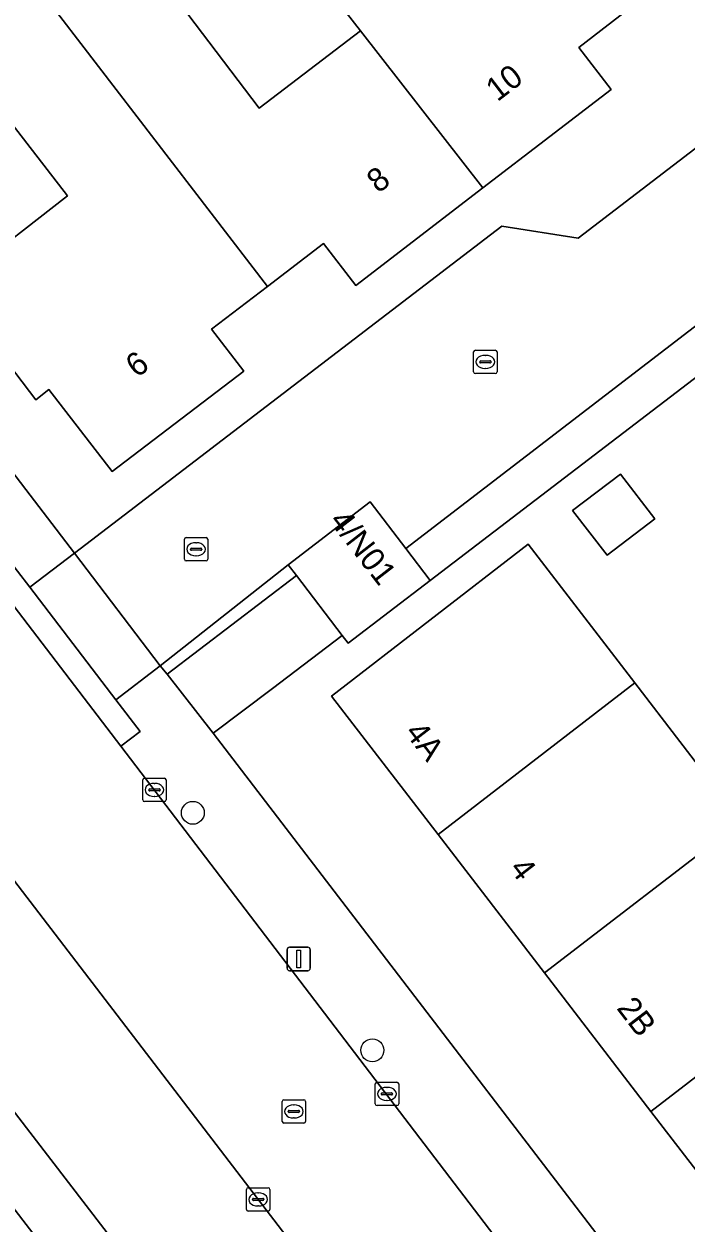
# Model space of a CAD drawing. Extents: x 159352 to 160617, y 385888 to 387323.
# Drawn here: x 159956.1 to 159984.4, y 386578.7 to 386630 of the extents above; entities that cross this region are included whole.
import ezdxf

# ---------------------------------------------------------------- set-up
doc = ezdxf.new("R2010")
doc.units = 0
for name, color, linetype in [('IMGEO_Boom', 7, 'Continuous'), ('IMGEO_Erf', 7, 'Continuous'), ('IMGEO_Kolk', 7, 'Continuous'), ('IMGEO_Lichtmast', 7, 'Continuous'), ('IMGEO_Pand', 7, 'Continuous'), ('IMGEO_Pand_nummerreeks', 7, 'Continuous'), ('IMGEO_Parkeervlak_open', 7, 'Continuous'), ('IMGEO_Rijbaan_lokaal_open', 7, 'Continuous'), ('IMGEO_Rioolput', 7, 'Continuous'), ('IMGEO_Voetpad_open', 7, 'Continuous')]:
    doc.layers.add(name, color=color, linetype=linetype)

msp = doc.modelspace()

# ---------------------------------------------------------------- linework, layer by layer
at = {"layer": 'IMGEO_Boom'}
for centre in [(159963.305, 386596.274), (159970.984, 386586.121)]:
    msp.add_circle(centre, 0.489, dxfattribs=at)
at = {"layer": 'IMGEO_Erf'}
for points in [[(159968.972, 386640.663), (159965.595, 386645.082), (159961.243, 386641.763), (159957.042, 386638.558), (159960.348, 386634.04), (159966.149, 386626.39), (159970.474, 386629.706), (159968.795, 386631.865), (159973.148, 386635.198)], [(159981.022, 386607.284), (159979.545, 386609.197), (159981.598, 386610.757), (159983.062, 386608.837)], [(160000.448, 386586.263), (159998.468, 386584.763), (159996.488, 386583.263), (160000.418, 386578.153), (159992.002, 386571.674), (159987.45, 386577.592), (159982.897, 386583.509), (159978.345, 386589.427), (159973.792, 386595.344), (159969.24, 386601.262), (159977.654, 386607.752), (159982.214, 386601.823), (159986.064, 386596.816), (159988.035, 386598.335), (159989.997, 386599.848), (159991.471, 386597.918), (159989.5, 386596.415), (159987.529, 386594.911), (159991.317, 386589.987), (159995.02, 386585.171), (159997.005, 386586.694), (159998.964, 386588.196)]]:
    msp.add_lwpolyline(points, close=True, dxfattribs=at)
for points in [[(159937.429, 386634.583), (159958.24, 386607.374), (159976.527, 386621.358), (159979.779, 386620.834), (159993.835, 386631.612), (159991.763, 386638.279), (160000, 386644.604)], [(159982.189, 386630.821), (159979.811, 386628.993), (159981.19, 386627.2), (159978.567, 386625.185), (159975.702, 386622.984), (159970.27, 386618.81), (159968.896, 386620.608), (159966.497, 386618.775), (159964.106, 386616.948), (159965.48, 386615.15), (159959.85, 386610.86), (159957.151, 386614.363), (159956.59, 386613.93), (159954.86, 386616.18), (159955.43, 386616.606), (159954.74, 386617.53), (159954.855, 386617.619), (159953.582, 386619.257), (159957.947, 386622.649), (159953.335, 386628.585), (159949.885, 386633.073), (159945.395, 386629.643), (159944.701, 386630.546)], [(160000, 386626.477), (159973.45, 386606.21), (159969.948, 386603.524), (159969.698, 386603.852), (159966.706, 386601.593), (159964.176, 386599.682), (159987.621, 386569.07)], [(159973.106, 386556.66), (159922.14, 386622.955)]]:
    msp.add_lwpolyline(points, dxfattribs=at)
at = {"layer": 'IMGEO_Kolk'}
for p, q in [((159975.315, 386615.124), (159975.315, 386615.976)), ((159975.39, 386616.05), (159976.242, 386616.05)), ((159975.617, 386615.593), (159976.015, 386615.593)), ((159975.803, 386615.83), (159975.828, 386615.83)), ((159976.316, 386615.976), (159976.316, 386615.124)), ((159975.574, 386615.544), (159975.574, 386615.556)), ((159976.012, 386615.507), (159975.614, 386615.507)), ((159975.826, 386615.27), (159975.801, 386615.27)), ((159976.058, 386615.556), (159976.058, 386615.544)), ((159976.242, 386615.05), (159975.39, 386615.05)), ((159962.944, 386607.113), (159962.944, 386607.965)), ((159963.019, 386608.039), (159963.871, 386608.039)), ((159963.945, 386607.965), (159963.945, 386607.113)), ((159963.203, 386607.533), (159963.203, 386607.545)), ((159963.641, 386607.496), (159963.243, 386607.496)), ((159963.246, 386607.582), (159963.644, 386607.582)), ((159963.432, 386607.819), (159963.457, 386607.819)), ((159963.687, 386607.545), (159963.687, 386607.533)), ((159963.871, 386607.039), (159963.019, 386607.039)), ((159963.455, 386607.259), (159963.43, 386607.259)), ((159961.163, 386596.825), (159961.163, 386597.677)), ((159961.238, 386597.751), (159962.09, 386597.751)), ((159962.164, 386597.677), (159962.164, 386596.825)), ((159961.422, 386597.245), (159961.422, 386597.257)), ((159961.86, 386597.208), (159961.462, 386597.208)), ((159961.465, 386597.294), (159961.863, 386597.294)), ((159961.651, 386597.531), (159961.676, 386597.531)), ((159961.906, 386597.257), (159961.906, 386597.245)), ((159962.09, 386596.751), (159961.238, 386596.751)), ((159961.674, 386596.971), (159961.649, 386596.971)), ((159971.108, 386583.83), (159971.108, 386584.682)), ((159971.183, 386584.756), (159972.035, 386584.756)), ((159971.596, 386584.536), (159971.621, 386584.536)), ((159972.109, 386584.682), (159972.109, 386583.83)), ((159971.367, 386584.25), (159971.367, 386584.262)), ((159971.805, 386584.213), (159971.407, 386584.213)), ((159971.41, 386584.299), (159971.808, 386584.299)), ((159971.619, 386583.976), (159971.594, 386583.976)), ((159971.851, 386584.262), (159971.851, 386584.25)), ((159972.035, 386583.756), (159971.183, 386583.756)), ((159965.674, 386580.245), (159966.526, 386580.245)), ((159965.599, 386579.319), (159965.599, 386580.171)), ((159965.858, 386579.739), (159965.858, 386579.751)), ((159965.901, 386579.788), (159966.299, 386579.788)), ((159966.087, 386580.025), (159966.112, 386580.025)), ((159966.342, 386579.751), (159966.342, 386579.739)), ((159966.6, 386580.171), (159966.6, 386579.319)), ((159966.526, 386579.245), (159965.674, 386579.245)), ((159966.296, 386579.702), (159965.898, 386579.702)), ((159966.11, 386579.465), (159966.085, 386579.465))]:
    msp.add_line(p, q, dxfattribs=at)
for points in [[(159975.315, 386615.124), (159975.315, 386615.976)], [(159975.39, 386616.05), (159976.242, 386616.05)], [(159976.316, 386615.976), (159976.316, 386615.124)], [(159976.242, 386615.05), (159975.39, 386615.05)], [(159962.944, 386607.113), (159962.944, 386607.965)], [(159963.019, 386608.039), (159963.871, 386608.039)], [(159963.945, 386607.965), (159963.945, 386607.113)], [(159963.871, 386607.039), (159963.019, 386607.039)], [(159961.163, 386596.825), (159961.163, 386597.677)], [(159961.238, 386597.751), (159962.09, 386597.751)], [(159962.164, 386597.677), (159962.164, 386596.825)], [(159962.09, 386596.751), (159961.238, 386596.751)], [(159971.108, 386583.83), (159971.108, 386584.682)], [(159971.183, 386584.756), (159972.035, 386584.756)], [(159972.109, 386584.682), (159972.109, 386583.83)], [(159972.035, 386583.756), (159971.183, 386583.756)], [(159965.674, 386580.245), (159966.526, 386580.245)], [(159965.599, 386579.319), (159965.599, 386580.171)], [(159966.6, 386580.171), (159966.6, 386579.319)], [(159966.526, 386579.245), (159965.674, 386579.245)]]:
    msp.add_lwpolyline(points, dxfattribs=at)
for centre, radius, start, end in [((159975.392, 386615.974), 0.0765, 91.552, 178.448), ((159975.392, 386615.974), 0.0765, 91.552, 178.448), ((159975.614, 386615.553), 0.0403, 85.8775, 175.7526), ((159976.019, 386615.555), 0.0386, 1.7309, 96.639), ((159976.24, 386615.974), 0.0765, 1.552, 88.448), ((159976.24, 386615.974), 0.0765, 1.552, 88.448), ((159975.392, 386615.126), 0.0765, 181.552, 268.448), ((159975.392, 386615.126), 0.0765, 181.552, 268.448), ((159975.611, 386615.543), 0.0366, 178.938, 274.7102), ((159976.015, 386615.55), 0.043, 264.8664, 352.4533), ((159976.24, 386615.126), 0.0765, 271.552, 358.448), ((159976.24, 386615.126), 0.0765, 271.552, 358.448), ((159963.021, 386607.963), 0.0765, 91.552, 178.448), ((159963.021, 386607.963), 0.0765, 91.552, 178.448), ((159963.869, 386607.963), 0.0765, 1.552, 88.448), ((159963.869, 386607.963), 0.0765, 1.552, 88.448), ((159963.243, 386607.542), 0.0403, 85.8775, 175.7526), ((159963.24, 386607.532), 0.0366, 178.938, 274.7102), ((159963.644, 386607.539), 0.043, 264.8664, 352.4533), ((159963.648, 386607.544), 0.0386, 1.7309, 96.639), ((159963.021, 386607.115), 0.0765, 181.552, 268.448), ((159963.021, 386607.115), 0.0765, 181.552, 268.448), ((159963.869, 386607.115), 0.0765, 271.552, 358.448), ((159963.869, 386607.115), 0.0765, 271.552, 358.448), ((159961.24, 386597.675), 0.0765, 91.552, 178.448), ((159961.24, 386597.675), 0.0765, 91.552, 178.448), ((159962.088, 386597.675), 0.0765, 1.552, 88.448), ((159962.088, 386597.675), 0.0765, 1.552, 88.448), ((159961.462, 386597.254), 0.0403, 85.8775, 175.7526), ((159961.459, 386597.244), 0.0366, 178.938, 274.7102), ((159961.863, 386597.251), 0.043, 264.8664, 352.4533), ((159961.867, 386597.256), 0.0386, 1.7309, 96.639), ((159961.24, 386596.827), 0.0765, 181.552, 268.448), ((159961.24, 386596.827), 0.0765, 181.552, 268.448), ((159962.088, 386596.827), 0.0765, 271.552, 358.448), ((159962.088, 386596.827), 0.0765, 271.552, 358.448), ((159971.185, 386584.68), 0.0765, 91.552, 178.448), ((159971.185, 386584.68), 0.0765, 91.552, 178.448), ((159972.033, 386584.68), 0.0765, 1.552, 88.448), ((159972.033, 386584.68), 0.0765, 1.552, 88.448), ((159971.185, 386583.832), 0.0765, 181.552, 268.448), ((159971.185, 386583.832), 0.0765, 181.552, 268.448), ((159971.407, 386584.259), 0.0403, 85.8775, 175.7526), ((159971.404, 386584.249), 0.0366, 178.938, 274.7102), ((159971.808, 386584.256), 0.043, 264.8664, 352.4533), ((159971.812, 386584.261), 0.0386, 1.7309, 96.639), ((159972.033, 386583.832), 0.0765, 271.552, 358.448), ((159972.033, 386583.832), 0.0765, 271.552, 358.448), ((159965.676, 386580.169), 0.0765, 91.552, 178.448), ((159965.676, 386580.169), 0.0765, 91.552, 178.448), ((159966.524, 386580.169), 0.0765, 1.552, 88.448), ((159966.524, 386580.169), 0.0765, 1.552, 88.448), ((159965.898, 386579.748), 0.0403, 85.8775, 175.7526), ((159965.895, 386579.738), 0.0366, 178.938, 274.7102), ((159966.299, 386579.745), 0.043, 264.8664, 352.4533), ((159966.303, 386579.75), 0.0386, 1.7309, 96.639), ((159965.676, 386579.321), 0.0765, 181.552, 268.448), ((159965.676, 386579.321), 0.0765, 181.552, 268.448), ((159966.524, 386579.321), 0.0765, 271.552, 358.448), ((159966.524, 386579.321), 0.0765, 271.552, 358.448)]:
    msp.add_arc(centre, radius, start, end, dxfattribs=at)
for centre, major_axis, ratio, start_param, end_param in [((159975.802, 386615.55), (-0.387, 0.002), 0.722429, 4.712389, 7.853982), ((159975.827, 386615.55), (-0.39, 0.002), 0.717154, 1.570796, 4.712389), ((159963.431, 386607.539), (-0.387, 0.002), 0.722429, 4.712389, 7.853982), ((159963.456, 386607.539), (-0.39, 0.002), 0.717154, 1.570796, 4.712389), ((159961.65, 386597.251), (-0.387, 0.002), 0.722429, 4.712389, 7.853982), ((159961.675, 386597.251), (-0.39, 0.002), 0.717154, 1.570796, 4.712389), ((159971.595, 386584.256), (-0.387, 0.002), 0.722429, 4.712389, 7.853982), ((159971.62, 386584.256), (-0.39, 0.002), 0.717154, 1.570796, 4.712389), ((159966.086, 386579.745), (-0.387, 0.002), 0.722429, 4.712389, 7.853982), ((159966.111, 386579.745), (-0.39, 0.002), 0.717154, 1.570796, 4.712389)]:
    msp.add_ellipse(centre, major_axis=major_axis, ratio=ratio, start_param=start_param, end_param=end_param, dxfattribs=at)
at = {"layer": 'IMGEO_Lichtmast'}
for p, q in [((159967.436, 386590.525), (159968.226, 386590.525)), ((159968.226, 386590.525), (159967.436, 386590.525)), ((159967.336, 386589.625), (159967.336, 386590.425)), ((159967.336, 386590.425), (159967.336, 386589.625)), ((159968.326, 386590.425), (159968.326, 386589.625)), ((159968.326, 386589.625), (159968.326, 386590.425)), ((159968.226, 386589.525), (159967.436, 386589.525)), ((159967.436, 386589.525), (159968.226, 386589.525))]:
    msp.add_line(p, q, dxfattribs=at)
msp.add_lwpolyline([(159967.756, 386590.4), (159967.906, 386590.4), (159967.906, 386589.65), (159967.756, 386589.65), (159967.756, 386590.4)], dxfattribs=at)
for centre, start, end in [((159967.436, 386590.425), 90, 180), ((159967.436, 386590.425), 90, 180), ((159968.226, 386590.425), 0, 90), ((159968.226, 386590.425), 360, 90), ((159967.436, 386589.625), 180, 270), ((159967.436, 386589.625), 180, 270), ((159968.226, 386589.625), 270, 0), ((159968.226, 386589.625), 270, 0)]:
    msp.add_arc(centre, 0.1, start, end, dxfattribs=at)
at = {"layer": 'IMGEO_Pand'}
for points in [[(159982.189, 386630.821), (159972.52, 386643.37), (159968.972, 386640.663), (159973.148, 386635.198), (159968.795, 386631.865), (159970.474, 386629.706), (159975.702, 386622.984), (159978.567, 386625.185), (159981.19, 386627.2), (159979.811, 386628.993)], [(159975.702, 386622.984), (159970.474, 386629.706), (159966.149, 386626.39), (159960.348, 386634.04), (159956.855, 386631.322), (159966.497, 386618.775), (159968.896, 386620.608), (159970.27, 386618.81)], [(159956.855, 386631.322), (159953.335, 386628.585), (159957.947, 386622.649), (159953.582, 386619.257), (159954.855, 386617.619), (159954.74, 386617.53), (159955.43, 386616.606), (159954.86, 386616.18), (159956.59, 386613.93), (159957.151, 386614.363), (159959.85, 386610.86), (159965.48, 386615.15), (159964.106, 386616.948), (159966.497, 386618.775)], [(159981.598, 386610.757), (159979.545, 386609.197), (159981.022, 386607.284), (159983.062, 386608.837)], [(159967.388, 386606.878), (159967.735, 386606.424), (159969.698, 386603.852), (159969.948, 386603.524), (159973.45, 386606.21), (159972.409, 386607.573), (159970.89, 386609.564)], [(159982.214, 386601.823), (159977.654, 386607.752), (159969.24, 386601.262), (159973.792, 386595.344)], [(159986.765, 386595.905), (159986.064, 386596.816), (159982.214, 386601.823), (159973.792, 386595.344), (159978.345, 386589.427)], [(159991.317, 386589.987), (159987.529, 386594.911), (159986.765, 386595.905), (159978.345, 386589.427), (159982.897, 386583.509)], [(159995.869, 386584.068), (159995.02, 386585.171), (159991.317, 386589.987), (159982.897, 386583.509), (159987.45, 386577.592)]]:
    msp.add_lwpolyline(points, close=True, dxfattribs=at)
at = {"layer": 'IMGEO_Parkeervlak_open'}
for points in [[(159977.383, 386565.02), (159950.703, 386599.839), (159931.787, 386624.553)], [(159931.288, 386622.222), (159927.899, 386619.615), (159971.446, 386562.962), (159974.502, 386565.275)]]:
    msp.add_lwpolyline(points, dxfattribs=at)
at = {"layer": 'IMGEO_Rijbaan_lokaal_open'}
for points in [[(160000, 386628.741), (160015.231, 386640.426), (160007.623, 386650.457), (160000, 386644.604), (159991.763, 386638.279), (159993.835, 386631.612), (159979.779, 386620.834), (159976.527, 386621.358), (159958.24, 386607.374), (159961.914, 386602.559), (159967.388, 386606.878), (159970.89, 386609.564), (159972.409, 386607.573)], [(159934.436, 386632.803), (159928.787, 386628.473), (159931.787, 386624.553), (159950.703, 386599.839), (159977.383, 386565.02), (159978.763, 386563.271), (159980.449, 386561.077), (159985.98, 386565.362), (159960.23, 386599.121), (159954.454, 386606.66), (159934.758, 386632.371), (159934.721, 386632.417)]]:
    msp.add_lwpolyline(points, close=True, dxfattribs=at)
at = {"layer": 'IMGEO_Rioolput'}
for p, q in [((159967.126, 386583.082), (159967.126, 386583.934)), ((159967.201, 386584.008), (159968.053, 386584.008)), ((159968.127, 386583.934), (159968.127, 386583.082)), ((159967.385, 386583.502), (159967.385, 386583.514)), ((159967.823, 386583.465), (159967.425, 386583.465)), ((159967.428, 386583.551), (159967.826, 386583.551)), ((159967.614, 386583.788), (159967.639, 386583.788)), ((159967.869, 386583.514), (159967.869, 386583.502)), ((159968.053, 386583.008), (159967.201, 386583.008)), ((159967.637, 386583.228), (159967.612, 386583.228))]:
    msp.add_line(p, q, dxfattribs=at)
for points in [[(159967.126, 386583.082), (159967.126, 386583.934)], [(159967.201, 386584.008), (159968.053, 386584.008)], [(159968.127, 386583.934), (159968.127, 386583.082)], [(159968.053, 386583.008), (159967.201, 386583.008)]]:
    msp.add_lwpolyline(points, dxfattribs=at)
for centre, radius, start, end in [((159967.203, 386583.932), 0.0765, 91.552, 178.448), ((159967.203, 386583.932), 0.0765, 91.552, 178.448), ((159968.051, 386583.932), 0.0765, 1.552, 88.448), ((159968.051, 386583.932), 0.0765, 1.552, 88.448), ((159967.425, 386583.511), 0.0403, 85.8775, 175.7526), ((159967.422, 386583.501), 0.0366, 178.938, 274.7102), ((159967.826, 386583.508), 0.043, 264.8664, 352.4533), ((159967.83, 386583.513), 0.0386, 1.7309, 96.639), ((159967.203, 386583.084), 0.0765, 181.552, 268.448), ((159967.203, 386583.084), 0.0765, 181.552, 268.448), ((159968.051, 386583.084), 0.0765, 271.552, 358.448), ((159968.051, 386583.084), 0.0765, 271.552, 358.448)]:
    msp.add_arc(centre, radius, start, end, dxfattribs=at)
for centre, major_axis, ratio, start_param, end_param in [((159967.613, 386583.508), (-0.387, 0.002), 0.722429, 4.712389, 7.853982), ((159967.638, 386583.508), (-0.39, 0.002), 0.717154, 1.570796, 4.712389)]:
    msp.add_ellipse(centre, major_axis=major_axis, ratio=ratio, start_param=start_param, end_param=end_param, dxfattribs=at)
at = {"layer": 'IMGEO_Voetpad_open'}
for points in [[(160000, 386626.477), (160013.533, 386636.86), (160016.316, 386638.995), (160015.782, 386639.699), (160015.231, 386640.426), (160000, 386628.741), (159972.409, 386607.573), (159973.45, 386606.21)], [(159956.329, 386605.923), (159955.28, 386607.292), (159954.454, 386606.66), (159960.23, 386599.121), (159961.056, 386599.753), (159960.019, 386601.107)], [(159958.24, 386607.374), (159956.329, 386605.923), (159960.019, 386601.107), (159961.914, 386602.559)], [(159961.914, 386602.559), (159962.211, 386602.204), (159967.735, 386606.424), (159967.388, 386606.878)], [(159969.698, 386603.852), (159967.735, 386606.424), (159962.211, 386602.204), (159964.176, 386599.682), (159966.706, 386601.593)], [(159962.211, 386602.204), (159961.914, 386602.559), (159960.019, 386601.107), (159961.056, 386599.753), (159960.23, 386599.121), (159985.98, 386565.362), (159988.838, 386567.467), (159987.679, 386568.993), (159987.659, 386569.019), (159987.64, 386569.044), (159987.621, 386569.07), (159964.176, 386599.682)]]:
    msp.add_lwpolyline(points, close=True, dxfattribs=at)
for points in [[(159934.436, 386632.803), (159934.721, 386632.417), (159934.758, 386632.371), (159954.454, 386606.66), (159955.28, 386607.292), (159956.329, 386605.923), (159958.24, 386607.374), (159937.429, 386634.583)], [(159922.14, 386622.955), (159973.106, 386556.66)], [(159974.502, 386565.275), (159971.446, 386562.962), (159927.899, 386619.615), (159931.288, 386622.222)]]:
    msp.add_lwpolyline(points, dxfattribs=at)

# ---------------------------------------------------------------- texts
at = {"layer": 'IMGEO_Pand_nummerreeks'}
for s, rotation, p in [('10', 37.5322, (159976.329, 386626.645)), ('8', 37.539, (159971.236, 386622.73)), ('6', 37.3053, (159960.919, 386614.842)), ('4/N01', 307.7468, (159969.108, 386608.743)), ('4A', 307.571, (159972.337, 386599.696)), ('4', 307.571, (159976.812, 386593.879)), ('2B', 307.571, (159981.4, 386587.915))]:
    msp.add_text(s, height=1, rotation=rotation, dxfattribs=at).set_placement(p)

doc.saveas('drawing.dxf')
